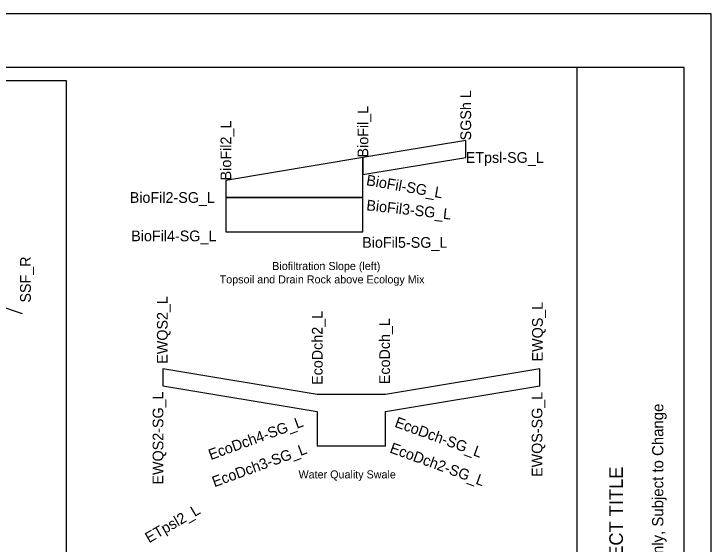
# Model space of a CAD drawing. Extents: x 0 to 1.42, y 0 to 0.92.
# Drawn here: x 0.874 to 1.417, y 0.504 to 0.917 of the extents above; entities that cross this region are included whole.
import ezdxf

# ---------------------------------------------------------------- set-up
doc = ezdxf.new("R2010")
doc.units = 0
for name, color, linetype in [('#plot_shape', 7, 'Continuous'), ('Level 63', 7, 'Continuous'), ('P_ODOT_PLAN_Border', 7, 'Continuous'), ('P_ODOT_PLAN_TBlock', 7, 'Continuous'), ('P_ODOT_PLAN_TBShtTitle', 7, 'Continuous'), ('P_ODOT_PLAN_TBStatus', 7, 'Continuous'), ('P_RDWY_PLAN_Detail', 7, 'Continuous'), ('P_RDWY_PLAN_DetailTx', 7, 'Continuous')]:
    doc.layers.add(name, color=color, linetype=linetype)

msp = doc.modelspace()

# ---------------------------------------------------------------- linework, layer by layer
at = {"layer": '#plot_shape'}
msp.add_lwpolyline([(0, 0), (1.41667, 0), (1.41667, 0.91667), (0, 0.91667)], close=True, dxfattribs=at)
msp.add_lwpolyline([(0, 0), (1.41667, 0), (1.41667, 0.91667), (0, 0.91667)], close=True, dxfattribs=at)
at = {"layer": 'Level 63'}
msp.add_lwpolyline([(0.91493, 0.24948), (0.07445, 0.24948), (0.07445, 0.86481), (0.91493, 0.86481)], close=True, dxfattribs=at)
at = {"layer": 'P_ODOT_PLAN_Border'}
msp.add_line((1.30879, 0.875), (0.0625, 0.875), dxfattribs=at)
msp.add_line((1.30879, 0.875), (0.0625, 0.875), dxfattribs=at)
msp.add_line((1.30879, 0.875), (0.0625, 0.875), dxfattribs=at)
msp.add_line((1.30879, 0.875), (0.0625, 0.875), dxfattribs=at)
msp.add_lwpolyline([(0.0625, 0.04167), (1.39583, 0.04167), (1.39583, 0.875), (0.0625, 0.875)], close=True, dxfattribs=at)
msp.add_lwpolyline([(0.0625, 0.04167), (1.39583, 0.04167), (1.39583, 0.875), (0.0625, 0.875)], close=True, dxfattribs=at)
at = {"layer": 'P_ODOT_PLAN_TBlock'}
msp.add_line((1.3125, 0.04167), (1.3125, 0.875), dxfattribs=at)
at = {"layer": 'P_RDWY_PLAN_Detail'}
for points in [[(1.22583, 0.81832), (1.14583, 0.80499), (1.14586, 0.79165), (1.2258, 0.80499)], [(1.14583, 0.80499), (1.03916, 0.78721), (1.03919, 0.77388), (1.1458, 0.77388)], [(1.1458, 0.77388), (1.03919, 0.77388), (1.03922, 0.74721), (1.14578, 0.74721)], [(1.28343, 0.64064), (1.16343, 0.62064), (1.1101, 0.62064), (0.9901, 0.64064), (0.99013, 0.62731), (1.1101, 0.60731), (1.11013, 0.58064), (1.16341, 0.58064), (1.16343, 0.60731), (1.28341, 0.62731)]]:
    msp.add_lwpolyline(points, close=True, dxfattribs=at)
msp.add_lwpolyline([(0.88102, 0.68347), (0.84148, 0.69665), (0.77481, 0.71298), (0.74148, 0.71365), (0.69148, 0.71465)], dxfattribs=at)

# ---------------------------------------------------------------- texts
at = {"layer": 'P_ODOT_PLAN_TBShtTitle'}
msp.add_text('PROJECT TITLE', height=0.0106, rotation=90, dxfattribs=at).set_placement((1.3481, 0.45582))
at = {"layer": 'P_ODOT_PLAN_TBStatus'}
msp.add_text('EBids - Information Only, Subject to Change', height=0.0087, rotation=90, dxfattribs=at).set_placement((1.37953, 0.3853))
at = {"layer": 'P_RDWY_PLAN_Detail'}
for s, p in [('Biofiltration Slope (left)', (1.07526, 0.71748)), ('Topsoil and Drain Rock above Ecology Mix', (1.03433, 0.70706)), ('Water Quality Swale', (1.0957, 0.55536))]:
    msp.add_text(s, height=0.00625, dxfattribs=at).set_placement(p)
at = {"layer": 'P_RDWY_PLAN_DetailTx'}
for s, rotation, p in [('SGSh L', 90, (1.23, 0.81832)), ('BioFil_L', 90, (1.15, 0.80499)), ('BioFil2_L', 90, (1.04333, 0.78721)), ('BioFil-SG_L', 350.0609, (1.14794, 0.78357)), ('BioFil3-SG_L', 353.6748, (1.14816, 0.76397)), ('SSF_R', 90, (0.88741, 0.69214)), ('EWQS2_L', 90, (0.99388, 0.64456)), ('EWQS_L', 90, (1.28574, 0.64637)), ('EcoDch2_L', 90, (1.11445, 0.62812)), ('EcoDch_L', 90, (1.16685, 0.62869)), ('EWQS2-SG_L', 90, (0.99052, 0.55061)), ('EWQS-SG_L', 90, (1.28543, 0.55652)), ('EcoDch4-SG_L', 20, (1.02743, 0.56958)), ('EcoDch-SG_L', 340, (1.1699, 0.59569)), ('EcoDch3-SG_L', 20, (1.03025, 0.54847)), ('EcoDch2-SG_L', 340, (1.16606, 0.57567)), ('ETpsl2_L', 30, (0.97935, 0.50489))]:
    msp.add_text(s, height=0.00833, rotation=rotation, dxfattribs=at).set_placement(p)
for s, p in [('ETpsl-SG_L', (1.2258, 0.80082)), ('BioFil2-SG_L', (0.96437, 0.76971)), ('BioFil4-SG_L', (0.9655, 0.73984)), ('BioFil5-SG_L', (1.14521, 0.73476))]:
    msp.add_text(s, height=0.00833, dxfattribs=at).set_placement(p)

doc.saveas('drawing.dxf')
